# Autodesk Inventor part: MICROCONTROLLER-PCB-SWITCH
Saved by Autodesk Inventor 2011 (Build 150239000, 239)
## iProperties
Created: 2007-09
Part Number: MICROCONTROLLER-PCB-SWITCH
Document SubType Name: Modeling
Density: 1 g/cm^3
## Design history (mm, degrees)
feature "Base1"
body "Solid1"
